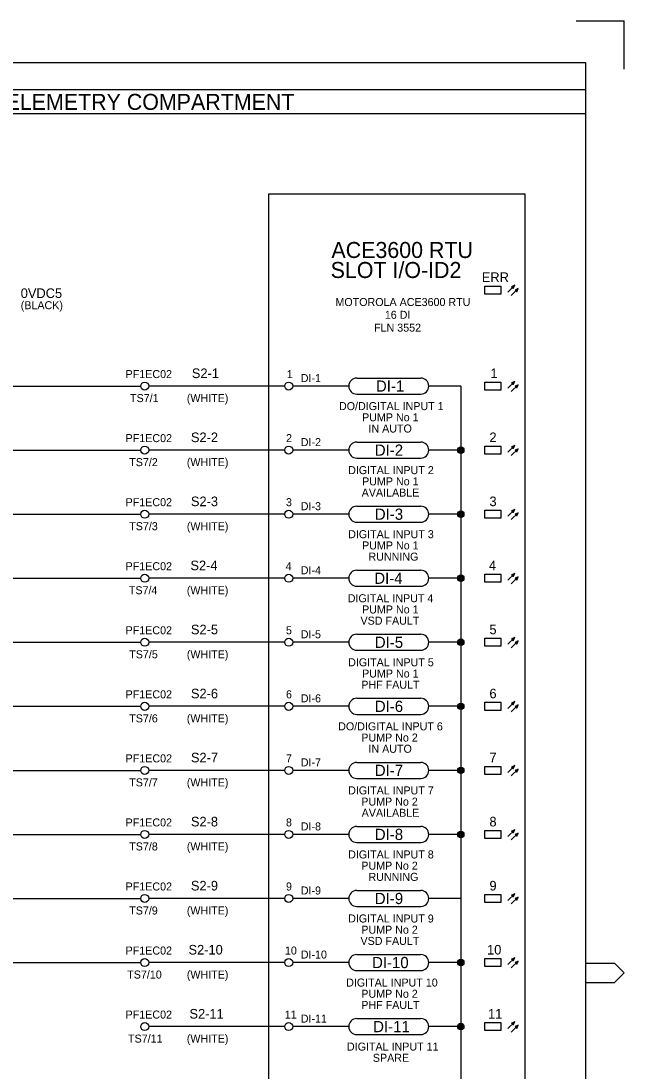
# Model space of a CAD drawing. Extents: x 0 to 841, y 0 to 594.
# Drawn here: x 652.6 to 841, y 266.1 to 594 of the extents above; entities that cross this region are included whole.
import ezdxf

# ---------------------------------------------------------------- set-up
doc = ezdxf.new("R2010")
doc.units = 0
for name, color, linetype in [('A1BORDER', 7, 'Continuous'), ('Level 1', 7, 'Continuous'), ('Level 10', 7, 'Continuous')]:
    doc.layers.add(name, color=color, linetype=linetype)

msp = doc.modelspace()

# ---------------------------------------------------------------- linework, layer by layer
at = {"layer": 'A1BORDER'}
for p, q in [((826, 594), (841, 594)), ((841, 579), (841, 594)), ((28, 581), (829, 581)), ((829, 581), (829, 15)), ((829, 299.76), (838, 299.76)), ((838, 299.76), (841, 296.76)), ((838, 293.76), (841, 296.76)), ((829, 293.76), (838, 293.76))]:
    msp.add_line(p, q, dxfattribs=at)
at = {"layer": 'Level 1'}
for p, q in [((829, 572.5), (160, 572.5)), ((829, 565), (160, 565)), ((757.5, 482.5), (777.5, 482.5)), ((522.5, 480), (690, 480)), ((735, 480), (692.5, 480)), ((755, 480), (737.5, 480)), ((790, 480), (780, 480)), ((790, 480), (790, 140)), ((757.5, 477.5), (777.5, 477.5)), ((757.5, 462.5), (777.5, 462.5)), ((485, 460), (690, 460)), ((735, 460), (692.5, 460)), ((755, 460), (737.5, 460)), ((790, 460), (780, 460)), ((757.5, 457.5), (777.5, 457.5)), ((485, 440), (690, 440)), ((735, 440), (692.5, 440)), ((755, 440), (737.5, 440)), ((757.5, 442.5), (777.5, 442.5)), ((790, 440), (780, 440)), ((757.5, 437.5), (777.5, 437.5)), ((485, 420), (690, 420)), ((735, 420), (692.5, 420)), ((755, 420), (737.5, 420)), ((757.5, 422.5), (777.5, 422.5)), ((790, 420), (780, 420)), ((757.5, 417.5), (777.5, 417.5)), ((757.5, 402.5), (777.5, 402.5)), ((485, 400), (690, 400)), ((735, 400), (692.5, 400)), ((755, 400), (737.5, 400)), ((757.5, 397.5), (777.5, 397.5)), ((790, 400), (780, 400)), ((757.5, 382.5), (777.5, 382.5)), ((522.5, 380), (690, 380)), ((735, 380), (692.5, 380)), ((755, 380), (737.5, 380)), ((757.5, 377.5), (777.5, 377.5)), ((790, 380), (780, 380)), ((757.5, 362.5), (777.5, 362.5)), ((485, 360), (690, 360)), ((735, 360), (692.5, 360)), ((755, 360), (737.5, 360)), ((757.5, 357.5), (777.5, 357.5)), ((790, 360), (780, 360)), ((757.5, 342.5), (777.5, 342.5)), ((485, 340), (690, 340)), ((735, 340), (692.5, 340)), ((755, 340), (737.5, 340)), ((790, 340), (780, 340)), ((757.5, 337.5), (777.5, 337.5)), ((757.5, 322.5), (777.5, 322.5)), ((485, 320), (690, 320)), ((735, 320), (692.5, 320)), ((755, 320), (737.5, 320)), ((790, 320), (780, 320)), ((757.5, 317.5), (777.5, 317.5)), ((757.5, 302.5), (777.5, 302.5)), ((485, 300), (690, 300)), ((735, 300), (692.5, 300)), ((755, 300), (737.5, 300)), ((790, 300), (780, 300)), ((757.5, 297.5), (777.5, 297.5)), ((757.5, 282.5), (777.5, 282.5)), ((735, 280), (692.5, 280)), ((755, 280), (737.5, 280)), ((790, 280), (780, 280)), ((757.5, 277.5), (777.5, 277.5))]:
    msp.add_line(p, q, dxfattribs=at)
for points in [[(730, 540), (810, 540), (810, 90), (730, 90)], [(797.5, 511.25), (802.5, 511.25), (802.5, 508.75), (797.5, 508.75)], [(797.5, 481.25), (802.5, 481.25), (802.5, 478.75), (797.5, 478.75)], [(797.5, 461.25), (802.5, 461.25), (802.5, 458.75), (797.5, 458.75)], [(797.5, 441.25), (802.5, 441.25), (802.5, 438.75), (797.5, 438.75)], [(797.5, 421.25), (802.5, 421.25), (802.5, 418.75), (797.5, 418.75)], [(797.5, 401.25), (802.5, 401.25), (802.5, 398.75), (797.5, 398.75)], [(797.5, 381.25), (802.5, 381.25), (802.5, 378.75), (797.5, 378.75)], [(797.5, 361.25), (802.5, 361.25), (802.5, 358.75), (797.5, 358.75)], [(797.5, 341.25), (802.5, 341.25), (802.5, 338.75), (797.5, 338.75)], [(797.5, 321.25), (802.5, 321.25), (802.5, 318.75), (797.5, 318.75)], [(797.5, 301.25), (802.5, 301.25), (802.5, 298.75), (797.5, 298.75)], [(797.5, 281.25), (802.5, 281.25), (802.5, 278.75), (797.5, 278.75)]]:
    msp.add_lwpolyline(points, close=True, dxfattribs=at)
for centre, start, end in [((757.5, 480), 90, 270), ((777.5, 480), 270, 90), ((757.5, 460), 90, 270), ((777.5, 460), 270, 90), ((757.5, 440), 90, 270), ((777.5, 440), 270, 90), ((757.5, 420), 90, 270), ((777.5, 420), 270, 90), ((757.5, 400), 90, 270), ((777.5, 400), 270, 90), ((757.5, 380), 90, 270), ((777.5, 380), 270, 90), ((757.5, 360), 90, 270), ((777.5, 360), 270, 90), ((757.5, 340), 90, 270), ((777.5, 340), 270, 90), ((757.5, 320), 90, 270), ((777.5, 320), 270, 90), ((757.5, 300), 90, 270), ((777.5, 300), 270, 90), ((757.5, 280), 90, 270), ((777.5, 280), 270, 90)]:
    msp.add_arc(centre, 2.5, start, end, dxfattribs=at)
at = {"layer": 'Level 10'}
for p, q in [((804.73, 509.36), (806.86, 511.48)), ((805.79, 508.3), (807.91, 510.42)), ((805.96, 511.07), (806.67, 511.07)), ((806, 510.93), (806.61, 510.93)), ((806.14, 510.78), (806.53, 510.78)), ((806.29, 511.23), (806.74, 511.23)), ((806.3, 510.62), (806.47, 510.62)), ((806.62, 511.38), (806.81, 511.38)), ((807.02, 510.01), (807.73, 510.01)), ((807.06, 509.87), (807.66, 509.87)), ((807.21, 509.72), (807.6, 509.72)), ((807.35, 510.17), (807.8, 510.17)), ((807.36, 509.56), (807.53, 509.56)), ((807.68, 510.31), (807.87, 510.31)), ((804.73, 479.36), (806.86, 481.48)), ((805.79, 478.3), (807.91, 480.42)), ((805.96, 481.07), (806.67, 481.07)), ((806, 480.93), (806.61, 480.93)), ((806.14, 480.78), (806.53, 480.78)), ((806.29, 481.23), (806.74, 481.23)), ((806.3, 480.62), (806.47, 480.62)), ((806.62, 481.38), (806.81, 481.38)), ((807.02, 480.01), (807.73, 480.01)), ((807.06, 479.87), (807.66, 479.87)), ((807.21, 479.72), (807.6, 479.72)), ((807.35, 480.17), (807.8, 480.17)), ((807.36, 479.56), (807.53, 479.56)), ((807.68, 480.31), (807.87, 480.31)), ((789.01, 460.1), (790.99, 460.1)), ((789.02, 459.8), (790.98, 459.8)), ((789.08, 460.4), (790.92, 460.4)), ((789.13, 459.5), (790.87, 459.5)), ((789.29, 460.7), (790.71, 460.7)), ((789.4, 459.2), (790.6, 459.2)), ((790, 461), (790, 461)), ((804.73, 459.36), (806.86, 461.48)), ((805.79, 458.3), (807.91, 460.42)), ((805.96, 461.07), (806.67, 461.07)), ((806, 460.93), (806.61, 460.93)), ((806.14, 460.78), (806.53, 460.78)), ((806.29, 461.23), (806.74, 461.23)), ((806.3, 460.62), (806.47, 460.62)), ((806.62, 461.38), (806.81, 461.38)), ((807.02, 460.01), (807.73, 460.01)), ((807.06, 459.87), (807.66, 459.87)), ((807.21, 459.72), (807.6, 459.72)), ((807.35, 460.17), (807.8, 460.17)), ((807.36, 459.56), (807.53, 459.56)), ((807.68, 460.31), (807.87, 460.31)), ((789.01, 440.1), (790.99, 440.1)), ((789.02, 439.8), (790.98, 439.8)), ((789.08, 440.4), (790.92, 440.4)), ((789.13, 439.5), (790.87, 439.5)), ((789.29, 440.7), (790.71, 440.7)), ((790, 441), (790, 441)), ((804.73, 439.36), (806.86, 441.48)), ((805.79, 438.3), (807.91, 440.42)), ((805.96, 441.07), (806.67, 441.07)), ((806, 440.93), (806.61, 440.93)), ((806.14, 440.78), (806.53, 440.78)), ((806.29, 441.23), (806.74, 441.23)), ((806.3, 440.62), (806.47, 440.62)), ((806.62, 441.38), (806.81, 441.38)), ((807.02, 440.01), (807.73, 440.01)), ((807.06, 439.87), (807.66, 439.87)), ((807.21, 439.72), (807.6, 439.72)), ((807.35, 440.17), (807.8, 440.17)), ((807.36, 439.56), (807.53, 439.56)), ((807.68, 440.31), (807.87, 440.31)), ((789.4, 439.2), (790.6, 439.2)), ((789.01, 420.1), (790.99, 420.1)), ((789.02, 419.8), (790.98, 419.8)), ((789.08, 420.4), (790.92, 420.4)), ((789.29, 420.7), (790.71, 420.7)), ((790, 421), (790, 421)), ((804.73, 419.36), (806.86, 421.48)), ((805.79, 418.3), (807.91, 420.42)), ((805.96, 421.07), (806.67, 421.07)), ((806, 420.93), (806.61, 420.93)), ((806.14, 420.78), (806.53, 420.78)), ((806.29, 421.23), (806.74, 421.23)), ((806.3, 420.62), (806.47, 420.62)), ((806.62, 421.38), (806.81, 421.38)), ((807.02, 420.01), (807.73, 420.01)), ((807.06, 419.87), (807.66, 419.87)), ((807.21, 419.72), (807.6, 419.72)), ((807.35, 420.17), (807.8, 420.17)), ((807.68, 420.31), (807.87, 420.31)), ((789.13, 419.5), (790.87, 419.5)), ((789.4, 419.2), (790.6, 419.2)), ((807.36, 419.56), (807.53, 419.56)), ((789.01, 400.1), (790.99, 400.1)), ((789.08, 400.4), (790.92, 400.4)), ((789.29, 400.7), (790.71, 400.7)), ((790, 401), (790, 401)), ((804.73, 399.36), (806.86, 401.48)), ((805.79, 398.3), (807.91, 400.42)), ((805.96, 401.07), (806.67, 401.07)), ((806, 400.93), (806.61, 400.93)), ((806.14, 400.78), (806.53, 400.78)), ((806.29, 401.23), (806.74, 401.23)), ((806.3, 400.62), (806.47, 400.62)), ((806.62, 401.38), (806.81, 401.38)), ((807.02, 400.01), (807.73, 400.01)), ((807.35, 400.17), (807.8, 400.17)), ((807.68, 400.31), (807.87, 400.31)), ((789.02, 399.8), (790.98, 399.8)), ((789.13, 399.5), (790.87, 399.5)), ((789.4, 399.2), (790.6, 399.2)), ((807.06, 399.87), (807.66, 399.87)), ((807.21, 399.72), (807.6, 399.72)), ((807.36, 399.56), (807.53, 399.56)), ((789.08, 380.4), (790.92, 380.4)), ((789.29, 380.7), (790.71, 380.7)), ((790, 381), (790, 381)), ((804.73, 379.36), (806.86, 381.48)), ((805.79, 378.3), (807.91, 380.42)), ((805.96, 381.07), (806.67, 381.07)), ((806, 380.93), (806.61, 380.93)), ((806.14, 380.78), (806.53, 380.78)), ((806.29, 381.23), (806.74, 381.23)), ((806.3, 380.62), (806.47, 380.62)), ((806.62, 381.38), (806.81, 381.38)), ((789.01, 380.1), (790.99, 380.1)), ((789.02, 379.8), (790.98, 379.8)), ((789.13, 379.5), (790.87, 379.5)), ((789.4, 379.2), (790.6, 379.2)), ((807.02, 380.01), (807.73, 380.01)), ((807.06, 379.87), (807.66, 379.87)), ((807.21, 379.72), (807.6, 379.72)), ((807.35, 380.17), (807.8, 380.17)), ((807.36, 379.56), (807.53, 379.56)), ((807.68, 380.31), (807.87, 380.31)), ((789.29, 360.7), (790.71, 360.7)), ((790, 361), (790, 361)), ((804.73, 359.36), (806.86, 361.48)), ((805.96, 361.07), (806.67, 361.07)), ((806, 360.93), (806.61, 360.93)), ((806.14, 360.78), (806.53, 360.78)), ((806.29, 361.23), (806.74, 361.23)), ((806.62, 361.38), (806.81, 361.38)), ((789.01, 360.1), (790.99, 360.1)), ((789.02, 359.8), (790.98, 359.8)), ((789.08, 360.4), (790.92, 360.4)), ((789.13, 359.5), (790.87, 359.5)), ((789.4, 359.2), (790.6, 359.2)), ((805.79, 358.3), (807.91, 360.42)), ((806.3, 360.62), (806.47, 360.62)), ((807.02, 360.01), (807.73, 360.01)), ((807.06, 359.87), (807.66, 359.87)), ((807.21, 359.72), (807.6, 359.72)), ((807.35, 360.17), (807.8, 360.17)), ((807.36, 359.56), (807.53, 359.56)), ((807.68, 360.31), (807.87, 360.31)), ((790, 341), (790, 341)), ((804.73, 339.36), (806.86, 341.48)), ((805.96, 341.07), (806.67, 341.07)), ((806.29, 341.23), (806.74, 341.23)), ((806.62, 341.38), (806.81, 341.38)), ((789.01, 340.1), (790.99, 340.1)), ((789.02, 339.8), (790.98, 339.8)), ((789.08, 340.4), (790.92, 340.4)), ((789.13, 339.5), (790.87, 339.5)), ((789.29, 340.7), (790.71, 340.7)), ((789.4, 339.2), (790.6, 339.2)), ((805.79, 338.3), (807.91, 340.42)), ((806, 340.93), (806.61, 340.93)), ((806.14, 340.78), (806.53, 340.78)), ((806.3, 340.62), (806.47, 340.62)), ((807.02, 340.01), (807.73, 340.01)), ((807.06, 339.87), (807.66, 339.87)), ((807.21, 339.72), (807.6, 339.72)), ((807.35, 340.17), (807.8, 340.17)), ((807.36, 339.56), (807.53, 339.56)), ((807.68, 340.31), (807.87, 340.31)), ((804.73, 319.36), (806.86, 321.48)), ((806.62, 321.38), (806.81, 321.38)), ((805.79, 318.3), (807.91, 320.42)), ((805.96, 321.07), (806.67, 321.07)), ((806, 320.93), (806.61, 320.93)), ((806.14, 320.78), (806.53, 320.78)), ((806.29, 321.23), (806.74, 321.23)), ((806.3, 320.62), (806.47, 320.62)), ((807.02, 320.01), (807.73, 320.01)), ((807.06, 319.87), (807.66, 319.87)), ((807.21, 319.72), (807.6, 319.72)), ((807.35, 320.17), (807.8, 320.17)), ((807.36, 319.56), (807.53, 319.56)), ((807.68, 320.31), (807.87, 320.31)), ((789.01, 300.1), (790.99, 300.1)), ((789.02, 299.8), (790.98, 299.8)), ((789.08, 300.4), (790.92, 300.4)), ((789.13, 299.5), (790.87, 299.5)), ((789.29, 300.7), (790.71, 300.7)), ((789.4, 299.2), (790.6, 299.2)), ((790, 301), (790, 301)), ((804.73, 299.36), (806.86, 301.48)), ((805.79, 298.3), (807.91, 300.42)), ((805.96, 301.07), (806.67, 301.07)), ((806, 300.93), (806.61, 300.93)), ((806.14, 300.78), (806.53, 300.78)), ((806.29, 301.23), (806.74, 301.23)), ((806.3, 300.62), (806.47, 300.62)), ((806.62, 301.38), (806.81, 301.38)), ((807.02, 300.01), (807.73, 300.01)), ((807.06, 299.87), (807.66, 299.87)), ((807.21, 299.72), (807.6, 299.72)), ((807.35, 300.17), (807.8, 300.17)), ((807.36, 299.56), (807.53, 299.56)), ((807.68, 300.31), (807.87, 300.31)), ((789.01, 280.1), (790.99, 280.1)), ((789.02, 279.8), (790.98, 279.8)), ((789.08, 280.4), (790.92, 280.4)), ((789.13, 279.5), (790.87, 279.5)), ((789.29, 280.7), (790.71, 280.7)), ((789.4, 279.2), (790.6, 279.2)), ((790, 281), (790, 281)), ((804.73, 279.36), (806.86, 281.48)), ((805.79, 278.3), (807.91, 280.42)), ((805.96, 281.07), (806.67, 281.07)), ((806, 280.93), (806.61, 280.93)), ((806.14, 280.78), (806.53, 280.78)), ((806.29, 281.23), (806.74, 281.23)), ((806.3, 280.62), (806.47, 280.62)), ((806.62, 281.38), (806.81, 281.38)), ((807.02, 280.01), (807.73, 280.01)), ((807.06, 279.87), (807.66, 279.87)), ((807.21, 279.72), (807.6, 279.72)), ((807.35, 280.17), (807.8, 280.17)), ((807.36, 279.56), (807.53, 279.56)), ((807.68, 280.31), (807.87, 280.31))]:
    msp.add_line(p, q, dxfattribs=at)
for points in [[(806.86, 511.48), (805.88, 511.04), (806.41, 510.5)], [(807.91, 510.42), (806.94, 509.98), (807.48, 509.44)], [(806.86, 481.48), (805.88, 481.04), (806.41, 480.5)], [(807.91, 480.42), (806.94, 479.98), (807.48, 479.44)], [(806.86, 461.48), (805.88, 461.04), (806.41, 460.5)], [(807.91, 460.42), (806.94, 459.98), (807.48, 459.44)], [(806.86, 441.48), (805.88, 441.04), (806.41, 440.5)], [(807.91, 440.42), (806.94, 439.98), (807.48, 439.44)], [(806.86, 421.48), (805.88, 421.04), (806.41, 420.5)], [(807.91, 420.42), (806.94, 419.98), (807.48, 419.44)], [(806.86, 401.48), (805.88, 401.04), (806.41, 400.5)], [(807.91, 400.42), (806.94, 399.98), (807.48, 399.44)], [(806.86, 381.48), (805.88, 381.04), (806.41, 380.5)], [(807.91, 380.42), (806.94, 379.98), (807.48, 379.44)], [(806.86, 361.48), (805.88, 361.04), (806.41, 360.5)], [(807.91, 360.42), (806.94, 359.98), (807.48, 359.44)], [(806.86, 341.48), (805.88, 341.04), (806.41, 340.5)], [(807.91, 340.42), (806.94, 339.98), (807.48, 339.44)], [(806.86, 321.48), (805.88, 321.04), (806.41, 320.5)], [(807.91, 320.42), (806.94, 319.98), (807.48, 319.44)], [(806.86, 301.48), (805.88, 301.04), (806.41, 300.5)], [(807.91, 300.42), (806.94, 299.98), (807.48, 299.44)], [(806.86, 281.48), (805.88, 281.04), (806.41, 280.5)], [(807.91, 280.42), (806.94, 279.98), (807.48, 279.44)]]:
    msp.add_lwpolyline(points, close=True, dxfattribs=at)
for centre, radius in [((691.25, 480), 1.25), ((736.25, 480), 1.25), ((691.25, 460), 1.25), ((736.25, 460), 1.25), ((790, 460), 1), ((691.25, 440), 1.25), ((736.25, 440), 1.25), ((790, 440), 1), ((691.25, 420), 1.25), ((736.25, 420), 1.25), ((790, 420), 1), ((691.25, 400), 1.25), ((736.25, 400), 1.25), ((790, 400), 1), ((691.25, 380), 1.25), ((736.25, 380), 1.25), ((790, 380), 1), ((691.25, 360), 1.25), ((736.25, 360), 1.25), ((790, 360), 1), ((691.25, 340), 1.25), ((736.25, 340), 1.25), ((790, 340), 1), ((691.25, 320), 1.25), ((736.25, 320), 1.25), ((691.25, 300), 1.25), ((736.25, 300), 1.25), ((790, 300), 1), ((691.25, 280), 1.25), ((736.25, 280), 1.25), ((790, 280), 1)]:
    msp.add_circle(centre, radius, dxfattribs=at)

# ---------------------------------------------------------------- texts
at = {"layer": 'Level 1'}
for s, height, p in [('TELEMETRY COMPARTMENT', 5, (643.66, 566.25)), ('ACE3600 RTU', 5, (749.58, 520)), ('SLOT I/O-ID2', 5, (749.33, 513.75)), ('ERR', 3, (796.56, 512.5)), ('0VDC5', 3, (652.5, 507.5)), ('(BLACK)', 2.5, (652.5, 504)), ('MOTOROLA ACE3600 RTU', 2.5, (750.83, 505)), ('16 DI', 2.5, (766.26, 501)), ('FLN 3552', 2.5, (762.9, 497)), ('S2-1', 3, (705.96, 482.5)), ('1', 3, (799.25, 482.5)), ('PF1EC02', 2.5, (685.27, 482.5)), ('1', 2.5, (735.63, 482.5)), ('DI-1', 2.5, (740, 481.25)), ('DI-1', 3.5, (763.49, 478.25)), ('TS7/1', 2.5, (686.65, 475)), ('(WHITE)', 2.5, (704.39, 475)), ('DO/DIGITAL INPUT 1', 2.5, (751.94, 472.5)), ('PUMP No 1', 2.5, (759.16, 469)), ('IN AUTO', 2.5, (761.15, 465.5)), ('PF1EC02', 2.5, (685.27, 462.5)), ('S2-2', 3, (705.67, 462.5)), ('2', 2.5, (735.38, 462.5)), ('DI-2', 2.5, (740, 461.25)), ('2', 3, (798.95, 462.5)), ('DI-2', 3.5, (763.14, 458.25)), ('TS7/2', 2.5, (686.4, 455)), ('(WHITE)', 2.5, (704.39, 455)), ('DIGITAL INPUT 2', 2.5, (754.8, 452.5)), ('PUMP No 1', 2.5, (759.16, 449)), ('AVAILABLE', 2.5, (759.03, 445.5)), ('PF1EC02', 2.5, (685.27, 442.5)), ('S2-3', 3, (705.67, 442.5)), ('3', 2.5, (735.38, 442.5)), ('DI-3', 2.5, (740, 441.25)), ('3', 3, (798.95, 442.5)), ('DI-3', 3.5, (763.14, 438.25)), ('TS7/3', 2.5, (686.4, 435)), ('(WHITE)', 2.5, (704.39, 435)), ('DIGITAL INPUT 3', 2.5, (754.8, 432.5)), ('PUMP No 1', 2.5, (759.16, 429)), ('RUNNING', 2.5, (761.15, 425.5)), ('PF1EC02', 2.5, (685.27, 422.5)), ('S2-4', 3, (705.52, 422.5)), ('4', 2.5, (735.25, 422.5)), ('DI-4', 2.5, (740, 421.25)), ('4', 3, (798.8, 422.5)), ('DI-4', 3.5, (762.97, 418.25)), ('TS7/4', 2.5, (686.28, 415)), ('(WHITE)', 2.5, (704.39, 415)), ('DIGITAL INPUT 4', 2.5, (754.68, 412.5)), ('PUMP No 1', 2.5, (759.16, 409)), ('VSD FAULT', 2.5, (758.66, 405.5)), ('PF1EC02', 2.5, (685.27, 402.5)), ('S2-5', 3, (705.67, 402.5)), ('5', 2.5, (735.38, 402.5)), ('DI-5', 2.5, (740, 401.25)), ('5', 3, (798.95, 402.5)), ('DI-5', 3.5, (763.14, 398.25)), ('TS7/5', 2.5, (686.4, 395)), ('(WHITE)', 2.5, (704.39, 395)), ('DIGITAL INPUT 5', 2.5, (754.8, 392.5)), ('PUMP No 1', 2.5, (759.16, 389)), ('PHF FAULT', 2.5, (758.91, 385.5)), ('PF1EC02', 2.5, (685.27, 382.5)), ('S2-6', 3, (705.67, 382.5)), ('6', 2.5, (735.38, 382.5)), ('DI-6', 2.5, (740, 381.25)), ('6', 3, (798.95, 382.5)), ('DI-6', 3.5, (763.14, 378.25)), ('TS7/6', 2.5, (686.4, 375)), ('(WHITE)', 2.5, (704.39, 375)), ('DO/DIGITAL INPUT 6', 2.5, (751.69, 372.5)), ('PUMP No 2', 2.5, (758.91, 369)), ('IN AUTO', 2.5, (761.15, 365.5)), ('PF1EC02', 2.5, (685.27, 362.5)), ('S2-7', 3, (705.67, 362.5)), ('7', 2.5, (735.38, 362.5)), ('7', 3, (798.95, 362.5)), ('DI-7', 2.5, (740, 361.25)), ('DI-7', 3.5, (763.14, 358.25)), ('TS7/7', 2.5, (686.4, 355)), ('(WHITE)', 2.5, (704.39, 355)), ('DIGITAL INPUT 7', 2.5, (754.8, 352.5)), ('PUMP No 2', 2.5, (758.91, 349)), ('AVAILABLE', 2.5, (759.03, 345.5)), ('PF1EC02', 2.5, (685.27, 342.5)), ('S2-8', 3, (705.67, 342.5)), ('8', 2.5, (735.38, 342.5)), ('8', 3, (798.95, 342.5)), ('DI-8', 2.5, (740, 341.25)), ('DI-8', 3.5, (763.14, 338.25)), ('TS7/8', 2.5, (686.4, 335)), ('(WHITE)', 2.5, (704.39, 335)), ('DIGITAL INPUT 8', 2.5, (754.8, 332.5)), ('PUMP No 2', 2.5, (758.91, 329)), ('RUNNING', 2.5, (761.15, 325.5)), ('PF1EC02', 2.5, (685.27, 322.5)), ('S2-9', 3, (705.67, 322.5)), ('9', 2.5, (735.38, 322.5)), ('9', 3, (798.95, 322.5)), ('DI-9', 2.5, (740, 321.25)), ('DI-9', 3.5, (763.14, 318.25)), ('TS7/9', 2.5, (686.4, 315)), ('(WHITE)', 2.5, (704.39, 315)), ('DIGITAL INPUT 9', 2.5, (754.8, 312.5)), ('PUMP No 2', 2.5, (758.91, 309)), ('PF1EC02', 2.5, (685.27, 302.5)), ('S2-10', 3, (704.92, 302.5)), ('10', 2.5, (735.05, 302.5)), ('VSD FAULT', 2.5, (758.66, 305.5)), ('10', 3, (798.21, 302.5)), ('DI-10', 2.5, (740, 301.25)), ('DI-10', 3.5, (762.27, 298.25)), ('TS7/10', 2.5, (685.78, 295)), ('(WHITE)', 2.5, (704.39, 295)), ('DIGITAL INPUT 10', 2.5, (754.18, 292.5)), ('PUMP No 2', 2.5, (758.91, 289)), ('S2-11', 3, (705.22, 282.5)), ('PHF FAULT', 2.5, (758.91, 285.5)), ('11', 3, (798.51, 282.5)), ('PF1EC02', 2.5, (685.27, 282.5)), ('11', 2.5, (735.01, 282.5)), ('DI-11', 2.5, (740, 281.25)), ('DI-11', 3.5, (762.62, 278.25)), ('TS7/11', 2.5, (686.03, 275)), ('(WHITE)', 2.5, (704.39, 275)), ('DIGITAL INPUT 11', 2.5, (754.43, 272.5)), ('SPARE', 2.5, (762.52, 269))]:
    msp.add_text(s, height=height, dxfattribs=at).set_placement(p)

doc.saveas('drawing.dxf')
